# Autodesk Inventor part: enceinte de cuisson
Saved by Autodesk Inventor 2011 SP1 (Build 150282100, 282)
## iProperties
Created: 2010-12
Part Number: enceinte de cuisson
Document SubType Name: Modeling
Designer: eric
Density: 1 g/cm^3
Author: eric
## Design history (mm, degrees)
feature "Base1"
node "Solide1"
node "Corps solides"
node "Corps surfaciques"
